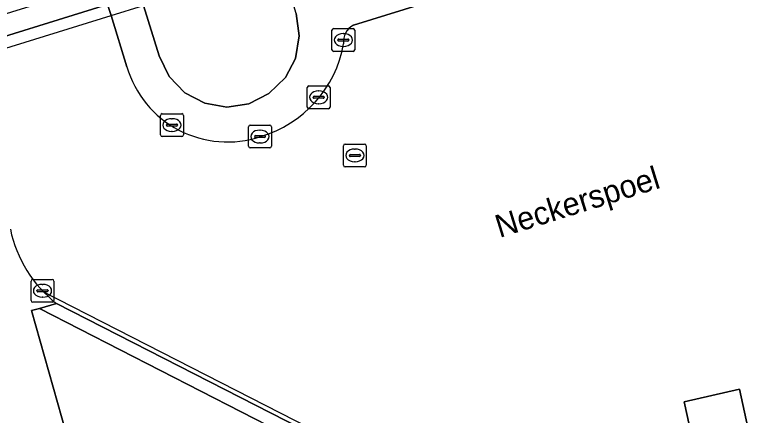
# Model space of a CAD drawing. Extents: x 160806 to 161707, y 383696 to 384148.
# Drawn here: x 161292.93 to 161325.17, y 383860.08 to 383877.62 of the extents above; entities that cross this region are included whole.
import ezdxf

# ---------------------------------------------------------------- set-up
doc = ezdxf.new("R2010")
doc.units = 0
for name, color, linetype in [('IMGEO_Dek', 7, 'Continuous'), ('IMGEO_Groenvoorziening', 7, 'Continuous'), ('IMGEO_Kolk', 7, 'Continuous'), ('IMGEO_Lijnafwatering', 7, 'Continuous'), ('IMGEO_Muur', 7, 'Continuous'), ('IMGEO_Openbare_ruimte_label', 7, 'Continuous'), ('IMGEO_OVBaan_gesloten', 7, 'Continuous'), ('IMGEO_Pand', 7, 'Continuous'), ('IMGEO_Rioolput', 7, 'Continuous'), ('IMGEO_Verkeerseiland_open', 7, 'Continuous'), ('IMGEO_Voetgangersgebied_open', 7, 'Continuous'), ('IMGEO_Voetpad_open', 7, 'Continuous')]:
    doc.layers.add(name, color=color, linetype=linetype)

msp = doc.modelspace()

# ---------------------------------------------------------------- linework, layer by layer
at = {"layer": 'IMGEO_Dek'}
msp.add_lwpolyline([(161302.038, 383887.98), (161301.743, 383888.915), (161301.62, 383889.306), (161295.624, 383887.436), (161294.221, 383887.002), (161287.509, 383884.926), (161284.106, 383883.873), (161278.902, 383882.264), (161278.108, 383882.018), (161278.23, 383881.626), (161278.509, 383880.732), (161280.618, 383873.97), (161280.9, 383873.066), (161281.046, 383872.599), (161281.82, 383872.838), (161287.026, 383874.44), (161290.463, 383875.507), (161297.147, 383877.582), (161298.569, 383878.023), (161304.585, 383879.891), (161304.435, 383880.368), (161304.154, 383881.259)], close=True, dxfattribs=at)
at = {"layer": 'IMGEO_Groenvoorziening'}
msp.add_lwpolyline([(161306.353, 383856.969), (161306.251, 383857.287), (161306.094, 383857.714), (161306.007, 383857.913), (161305.848, 383858.21), (161305.568, 383858.58), (161305.42, 383858.72), (161305.042, 383859.009), (161304.884, 383859.122), (161304.613, 383859.317), (161294.013, 383864.756), (161293.666, 383864.66), (161295.556, 383857.951), (161300.564, 383840.178), (161300.779, 383840.103), (161310.825, 383836.547), (161309.366, 383843.209)], close=True, dxfattribs=at)
at = {"layer": 'IMGEO_Kolk'}
for p, q in [((161306.816, 383876.083), (161306.816, 383876.935)), ((161306.891, 383877.009), (161307.743, 383877.009)), ((161307.304, 383876.789), (161307.329, 383876.789)), ((161307.817, 383876.935), (161307.817, 383876.083)), ((161307.075, 383876.503), (161307.075, 383876.515)), ((161307.513, 383876.466), (161307.115, 383876.466)), ((161307.118, 383876.552), (161307.516, 383876.552)), ((161307.559, 383876.515), (161307.559, 383876.503)), ((161307.327, 383876.229), (161307.302, 383876.229)), ((161307.743, 383876.009), (161306.891, 383876.009)), ((161305.809, 383874.501), (161306.661, 383874.501)), ((161305.734, 383873.575), (161305.734, 383874.427)), ((161306.222, 383874.281), (161306.247, 383874.281)), ((161306.735, 383874.427), (161306.735, 383873.575)), ((161305.993, 383873.995), (161305.993, 383874.007)), ((161306.431, 383873.958), (161306.033, 383873.958)), ((161306.036, 383874.044), (161306.434, 383874.044)), ((161306.477, 383874.007), (161306.477, 383873.995)), ((161306.245, 383873.721), (161306.22, 383873.721)), ((161299.311, 383872.358), (161299.311, 383873.21)), ((161299.386, 383873.284), (161300.238, 383873.284)), ((161300.312, 383873.21), (161300.312, 383872.358)), ((161306.661, 383873.501), (161305.809, 383873.501)), ((161299.799, 383873.064), (161299.824, 383873.064)), ((161299.57, 383872.778), (161299.57, 383872.79)), ((161300.008, 383872.741), (161299.61, 383872.741)), ((161299.613, 383872.827), (161300.011, 383872.827)), ((161300.054, 383872.79), (161300.054, 383872.778)), ((161303.165, 383871.857), (161303.165, 383872.709)), ((161303.24, 383872.783), (161304.092, 383872.783)), ((161303.653, 383872.563), (161303.678, 383872.563)), ((161304.166, 383872.709), (161304.166, 383871.857)), ((161300.238, 383872.284), (161299.386, 383872.284)), ((161299.822, 383872.504), (161299.797, 383872.504)), ((161303.424, 383872.277), (161303.424, 383872.289)), ((161303.862, 383872.24), (161303.464, 383872.24)), ((161303.467, 383872.326), (161303.865, 383872.326)), ((161303.908, 383872.289), (161303.908, 383872.277)), ((161303.676, 383872.003), (161303.651, 383872.003)), ((161304.092, 383871.783), (161303.24, 383871.783)), ((161293.646, 383865.101), (161293.646, 383865.953)), ((161293.721, 383866.027), (161294.573, 383866.027)), ((161294.134, 383865.807), (161294.159, 383865.807)), ((161294.647, 383865.953), (161294.647, 383865.101)), ((161293.905, 383865.521), (161293.905, 383865.533)), ((161294.343, 383865.484), (161293.945, 383865.484)), ((161293.948, 383865.57), (161294.346, 383865.57)), ((161294.389, 383865.533), (161294.389, 383865.521)), ((161294.157, 383865.247), (161294.132, 383865.247)), ((161294.573, 383865.027), (161293.721, 383865.027))]:
    msp.add_line(p, q, dxfattribs=at)
for points in [[(161306.816, 383876.083), (161306.816, 383876.935)], [(161306.891, 383877.009), (161307.743, 383877.009)], [(161307.817, 383876.935), (161307.817, 383876.083)], [(161307.743, 383876.009), (161306.891, 383876.009)], [(161305.809, 383874.501), (161306.661, 383874.501)], [(161305.734, 383873.575), (161305.734, 383874.427)], [(161306.735, 383874.427), (161306.735, 383873.575)], [(161299.311, 383872.358), (161299.311, 383873.21)], [(161299.386, 383873.284), (161300.238, 383873.284)], [(161300.312, 383873.21), (161300.312, 383872.358)], [(161306.661, 383873.501), (161305.809, 383873.501)], [(161303.165, 383871.857), (161303.165, 383872.709)], [(161303.24, 383872.783), (161304.092, 383872.783)], [(161304.166, 383872.709), (161304.166, 383871.857)], [(161300.238, 383872.284), (161299.386, 383872.284)], [(161304.092, 383871.783), (161303.24, 383871.783)], [(161293.646, 383865.101), (161293.646, 383865.953)], [(161293.721, 383866.027), (161294.573, 383866.027)], [(161294.647, 383865.953), (161294.647, 383865.101)], [(161294.573, 383865.027), (161293.721, 383865.027)]]:
    msp.add_lwpolyline(points, dxfattribs=at)
for centre, radius, start, end in [((161306.893, 383876.933), 0.0765, 91.552, 178.448), ((161306.893, 383876.933), 0.0765, 91.552, 178.448), ((161307.741, 383876.933), 0.0765, 1.552, 88.448), ((161307.741, 383876.933), 0.0765, 1.552, 88.448), ((161307.115, 383876.512), 0.0403, 85.8775, 175.7526), ((161307.112, 383876.502), 0.0366, 178.938, 274.7102), ((161307.516, 383876.509), 0.043, 264.8664, 352.4533), ((161307.52, 383876.514), 0.0386, 1.7309, 96.639), ((161306.893, 383876.085), 0.0765, 181.552, 268.448), ((161306.893, 383876.085), 0.0765, 181.552, 268.448), ((161307.741, 383876.085), 0.0765, 271.552, 358.448), ((161307.741, 383876.085), 0.0765, 271.552, 358.448), ((161305.811, 383874.425), 0.0765, 91.552, 178.448), ((161305.811, 383874.425), 0.0765, 91.552, 178.448), ((161306.659, 383874.425), 0.0765, 1.552, 88.448), ((161306.659, 383874.425), 0.0765, 1.552, 88.448), ((161306.033, 383874.004), 0.0403, 85.8775, 175.7526), ((161306.03, 383873.994), 0.0366, 178.938, 274.7102), ((161306.434, 383874.001), 0.043, 264.8664, 352.4533), ((161306.438, 383874.006), 0.0386, 1.7309, 96.639), ((161305.811, 383873.577), 0.0765, 181.552, 268.448), ((161305.811, 383873.577), 0.0765, 181.552, 268.448), ((161306.659, 383873.577), 0.0765, 271.552, 358.448), ((161306.659, 383873.577), 0.0765, 271.552, 358.448), ((161299.388, 383873.208), 0.0765, 91.552, 178.448), ((161299.388, 383873.208), 0.0765, 91.552, 178.448), ((161300.236, 383873.208), 0.0765, 1.552, 88.448), ((161300.236, 383873.208), 0.0765, 1.552, 88.448), ((161299.61, 383872.787), 0.0403, 85.8775, 175.7526), ((161299.607, 383872.777), 0.0366, 178.938, 274.7102), ((161300.011, 383872.784), 0.043, 264.8664, 352.4533), ((161300.015, 383872.789), 0.0386, 1.7309, 96.639), ((161303.242, 383872.707), 0.0765, 91.552, 178.448), ((161303.242, 383872.707), 0.0765, 91.552, 178.448), ((161304.09, 383872.707), 0.0765, 1.552, 88.448), ((161304.09, 383872.707), 0.0765, 1.552, 88.448), ((161299.388, 383872.36), 0.0765, 181.552, 268.448), ((161299.388, 383872.36), 0.0765, 181.552, 268.448), ((161300.236, 383872.36), 0.0765, 271.552, 358.448), ((161300.236, 383872.36), 0.0765, 271.552, 358.448), ((161303.464, 383872.286), 0.0403, 85.8775, 175.7526), ((161303.461, 383872.276), 0.0366, 178.938, 274.7102), ((161303.865, 383872.283), 0.043, 264.8664, 352.4533), ((161303.869, 383872.288), 0.0386, 1.7309, 96.639), ((161303.242, 383871.859), 0.0765, 181.552, 268.448), ((161303.242, 383871.859), 0.0765, 181.552, 268.448), ((161304.09, 383871.859), 0.0765, 271.552, 358.448), ((161304.09, 383871.859), 0.0765, 271.552, 358.448), ((161293.723, 383865.951), 0.0765, 91.552, 178.448), ((161293.723, 383865.951), 0.0765, 91.552, 178.448), ((161294.571, 383865.951), 0.0765, 1.552, 88.448), ((161294.571, 383865.951), 0.0765, 1.552, 88.448), ((161293.945, 383865.53), 0.0403, 85.8775, 175.7526), ((161293.942, 383865.52), 0.0366, 178.938, 274.7102), ((161294.346, 383865.527), 0.043, 264.8664, 352.4533), ((161294.35, 383865.532), 0.0386, 1.7309, 96.639), ((161293.723, 383865.103), 0.0765, 181.552, 268.448), ((161293.723, 383865.103), 0.0765, 181.552, 268.448), ((161294.571, 383865.103), 0.0765, 271.552, 358.448), ((161294.571, 383865.103), 0.0765, 271.552, 358.448)]:
    msp.add_arc(centre, radius, start, end, dxfattribs=at)
for centre, major_axis, ratio, start_param, end_param in [((161307.303, 383876.509), (-0.387, 0.002), 0.722429, 4.712389, 7.853982), ((161307.328, 383876.509), (-0.39, 0.002), 0.717154, 1.570796, 4.712389), ((161306.221, 383874.001), (-0.387, 0.002), 0.722429, 4.712389, 7.853982), ((161306.246, 383874.001), (-0.39, 0.002), 0.717154, 1.570796, 4.712389), ((161299.798, 383872.784), (-0.387, 0.002), 0.722429, 4.712389, 7.853982), ((161299.823, 383872.784), (-0.39, 0.002), 0.717154, 1.570796, 4.712389), ((161303.652, 383872.283), (-0.387, 0.002), 0.722429, 4.712389, 7.853982), ((161303.677, 383872.283), (-0.39, 0.002), 0.717154, 1.570796, 4.712389), ((161294.133, 383865.527), (-0.387, 0.002), 0.722429, 4.712389, 7.853982), ((161294.158, 383865.527), (-0.39, 0.002), 0.717154, 1.570796, 4.712389)]:
    msp.add_ellipse(centre, major_axis=major_axis, ratio=ratio, start_param=start_param, end_param=end_param, dxfattribs=at)
at = {"layer": 'IMGEO_Lijnafwatering'}
msp.add_lwpolyline([(161307.162, 383858.838), (161294.177, 383865.476)], dxfattribs=at)
at = {"layer": 'IMGEO_Muur'}
msp.add_lwpolyline([(161297.147, 383877.582), (161298.569, 383878.023), (161304.585, 383879.891), (161304.435, 383880.368), (161298.419, 383878.501), (161296.998, 383878.06), (161290.313, 383875.986), (161286.877, 383874.92), (161281.672, 383873.306), (161280.9, 383873.066), (161281.046, 383872.599), (161281.82, 383872.838), (161287.026, 383874.44), (161290.463, 383875.507)], close=True, dxfattribs=at)
at = {"layer": 'IMGEO_OVBaan_gesloten'}
for points in [[(161297.843, 383875.338), (161297.147, 383877.582), (161296.998, 383878.06), (161296.72, 383878.957), (161294.632, 383885.679), (161294.34, 383886.62), (161294.221, 383887.002), (161291.435, 383895.973)], [(161346.876, 383889.332), (161346.451, 383889.201), (161331.565, 383884.581), (161326.342, 383882.967), (161326.277, 383882.947), (161320.066, 383880.988), (161307.755, 383877.154)], [(161294.766, 383864.965), (161306.161, 383859.14), (161308.495, 383857.947), (161310.937, 383846.72), (161312.307, 383840.422)]]:
    msp.add_lwpolyline(points, dxfattribs=at)
msp.add_lwpolyline([(161329.684, 383838.129), (161327.285, 383837.621), (161324.629, 383849.738), (161322.234, 383860.665), (161324.648, 383861.218), (161327.036, 383850.268)], close=True, dxfattribs=at)
for centre, radius, start, end in [((161308.094, 383876.457), 0.775, 115.927, 188.8282), ((161302.23, 383877.252), 5.179, 286.3359, 349.8366), ((161302.234, 383876.619), 4.574, 196.2647, 288.5225), ((161298.191, 383869.353), 5.566, 191.6904, 232.0292)]:
    msp.add_arc(centre, radius, start, end, dxfattribs=at)
at = {"layer": 'IMGEO_Pand'}
for points in [[(161305.221, 383875.707), (161305.383, 383876.689), (161305.243, 383877.676), (161304.585, 383879.891), (161304.435, 383880.368), (161304.154, 383881.259), (161302.038, 383887.98), (161301.743, 383888.915), (161301.62, 383889.306), (161321.004, 383895.352), (161321.776, 383896.787), (161306.059, 383905.099), (161305.902, 383904.803), (161303.144, 383903.945), (161302.908, 383904.083), (161302.675, 383903.641), (161297.622, 383902.04), (161297.351, 383902.908), (161296.551, 383901.496)], [(161294.446, 383897.292), (161293.245, 383895.038), (161295.624, 383887.436), (161298.569, 383878.023), (161299.26, 383875.816), (161299.686, 383874.916), (161300.38, 383874.2), (161301.246, 383873.751), (161302.21, 383873.571), (161303.173, 383873.717), (161304.058, 383874.166), (161304.783, 383874.861), (161305.221, 383875.707)]]:
    msp.add_lwpolyline(points, dxfattribs=at)
at = {"layer": 'IMGEO_Rioolput'}
for p, q in [((161307.394, 383871.955), (161308.246, 383871.955)), ((161307.319, 383871.029), (161307.319, 383871.881)), ((161307.807, 383871.735), (161307.832, 383871.735)), ((161308.32, 383871.881), (161308.32, 383871.029)), ((161307.578, 383871.449), (161307.578, 383871.461)), ((161308.016, 383871.412), (161307.618, 383871.412)), ((161307.621, 383871.498), (161308.019, 383871.498)), ((161308.062, 383871.461), (161308.062, 383871.449)), ((161308.246, 383870.955), (161307.394, 383870.955)), ((161307.83, 383871.175), (161307.805, 383871.175))]:
    msp.add_line(p, q, dxfattribs=at)
for points in [[(161307.394, 383871.955), (161308.246, 383871.955)], [(161307.319, 383871.029), (161307.319, 383871.881)], [(161308.32, 383871.881), (161308.32, 383871.029)], [(161308.246, 383870.955), (161307.394, 383870.955)]]:
    msp.add_lwpolyline(points, dxfattribs=at)
for centre, radius, start, end in [((161307.396, 383871.879), 0.0765, 91.552, 178.448), ((161307.396, 383871.879), 0.0765, 91.552, 178.448), ((161308.244, 383871.879), 0.0765, 1.552, 88.448), ((161308.244, 383871.879), 0.0765, 1.552, 88.448), ((161307.618, 383871.458), 0.0403, 85.8775, 175.7526), ((161307.615, 383871.448), 0.0366, 178.938, 274.7102), ((161308.019, 383871.455), 0.043, 264.8664, 352.4533), ((161308.023, 383871.46), 0.0386, 1.7309, 96.639), ((161307.396, 383871.031), 0.0765, 181.552, 268.448), ((161307.396, 383871.031), 0.0765, 181.552, 268.448), ((161308.244, 383871.031), 0.0765, 271.552, 358.448), ((161308.244, 383871.031), 0.0765, 271.552, 358.448)]:
    msp.add_arc(centre, radius, start, end, dxfattribs=at)
for centre, major_axis, ratio, start_param, end_param in [((161307.806, 383871.455), (-0.387, 0.002), 0.722429, 4.712389, 7.853982), ((161307.831, 383871.455), (-0.39, 0.002), 0.717154, 1.570796, 4.712389)]:
    msp.add_ellipse(centre, major_axis=major_axis, ratio=ratio, start_param=start_param, end_param=end_param, dxfattribs=at)
at = {"layer": 'IMGEO_Verkeerseiland_open'}
msp.add_lwpolyline([(161329.684, 383838.129), (161327.036, 383850.268), (161324.648, 383861.218), (161322.234, 383860.665), (161324.629, 383849.738), (161327.285, 383837.621)], close=True, dxfattribs=at)
at = {"layer": 'IMGEO_Voetgangersgebied_open'}
msp.add_lwpolyline([(161325.598, 383831.395), (161320.903, 383833.041), (161317.419, 383834.272), (161311.124, 383836.441), (161310.825, 383836.547), (161300.779, 383840.103), (161300.564, 383840.178), (161295.556, 383857.951), (161293.666, 383864.66), (161294.013, 383864.756), (161294.766, 383864.965)], dxfattribs=at)
msp.add_arc((161298.191, 383869.353), 5.566, 191.6904, 232.0292, dxfattribs=at)
at = {"layer": 'IMGEO_Voetpad_open'}
for points in [[(161291.435, 383895.973), (161294.221, 383887.002), (161294.34, 383886.62), (161294.632, 383885.679), (161296.72, 383878.957), (161296.998, 383878.06), (161297.147, 383877.582), (161297.843, 383875.338)], [(161307.755, 383877.154), (161320.066, 383880.988)], [(161305.243, 383877.676), (161305.383, 383876.689), (161305.221, 383875.707), (161304.783, 383874.861), (161304.058, 383874.166), (161303.173, 383873.717), (161302.21, 383873.571), (161301.246, 383873.751), (161300.38, 383874.2), (161299.686, 383874.916), (161299.26, 383875.816), (161298.569, 383878.023)]]:
    msp.add_lwpolyline(points, dxfattribs=at)
for points in [[(161296.998, 383878.06), (161298.419, 383878.501), (161304.435, 383880.368), (161304.154, 383881.259), (161298.139, 383879.396), (161296.72, 383878.957), (161290.031, 383876.885), (161286.598, 383875.822), (161281.392, 383874.209), (161280.618, 383873.97), (161280.9, 383873.066), (161281.672, 383873.306), (161286.877, 383874.92), (161290.313, 383875.986)], [(161306.161, 383859.14), (161294.766, 383864.965), (161294.013, 383864.756), (161304.613, 383859.317), (161304.884, 383859.122), (161305.042, 383859.009), (161305.42, 383858.72), (161305.568, 383858.58), (161305.848, 383858.21), (161306.007, 383857.913), (161306.094, 383857.714), (161306.251, 383857.287), (161306.353, 383856.969), (161309.366, 383843.209), (161310.825, 383836.547), (161311.124, 383836.441), (161308.971, 383846.287)]]:
    msp.add_lwpolyline(points, close=True, dxfattribs=at)
for centre, radius, start, end in [((161308.094, 383876.457), 0.775, 115.927, 188.8282), ((161302.23, 383877.252), 5.179, 286.3359, 349.8366), ((161302.234, 383876.619), 4.574, 196.2647, 288.5225)]:
    msp.add_arc(centre, radius, start, end, dxfattribs=at)

# ---------------------------------------------------------------- texts
at = {"layer": 'IMGEO_Openbare_ruimte_label'}
msp.add_text('Neckerspoel', height=1, rotation=17.2754, dxfattribs=at).set_placement((161314.15, 383867.839))

doc.saveas('drawing.dxf')
